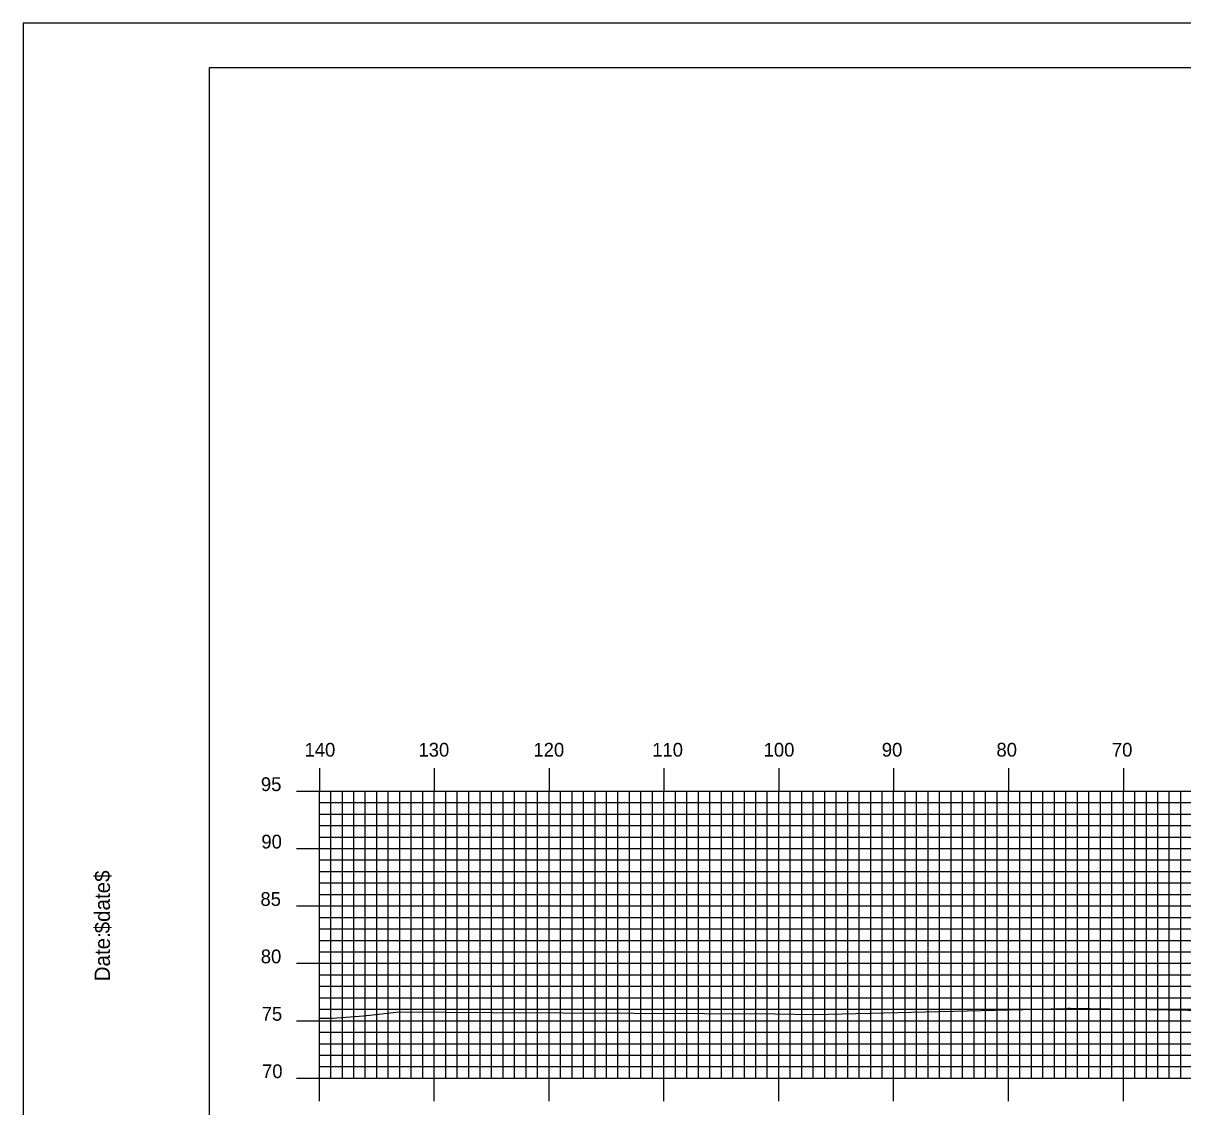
# Model space of a CAD drawing. Extents: x 1776744 to 1777088, y 442591 to 442811.
# Drawn here: x 1776744.5 to 1776845.4, y 442716.2 to 442810.5 of the extents above; entities that cross this region are included whole.
import ezdxf

# ---------------------------------------------------------------- set-up
doc = ezdxf.new("R2010")
doc.units = 0
for name, color, linetype in [('BORDER', 7, 'Continuous'), ('H_V ANNOTATION', 7, 'Continuous'), ('MAJOR', 7, 'Continuous'), ('MINOR', 7, 'Continuous'), ('PLOT BOUNDARY', 7, 'Continuous'), ('S_Roadway_Centerline', 7, 'Continuous')]:
    doc.layers.add(name, color=color, linetype=linetype)

msp = doc.modelspace()

# ---------------------------------------------------------------- linework, layer by layer
at = {"layer": 'BORDER'}
msp.add_lwpolyline([(1776760.65, 442596.67), (1777080.65, 442596.67), (1777080.65, 442806.67), (1776760.65, 442806.67)], close=True, dxfattribs=at)
at = {"layer": 'MAJOR'}
for p, q in [((1776770.25, 442745.67), (1776770.25, 442743.67)), ((1776780.25, 442745.67), (1776780.25, 442743.67)), ((1776790.25, 442745.67), (1776790.25, 442743.67)), ((1776800.25, 442745.67), (1776800.25, 442743.67)), ((1776810.25, 442745.67), (1776810.25, 442743.67)), ((1776820.25, 442745.67), (1776820.25, 442743.67)), ((1776830.25, 442745.67), (1776830.25, 442743.67)), ((1776840.25, 442745.67), (1776840.25, 442743.67)), ((1776768.25, 442743.67), (1776770.25, 442743.67)), ((1776770.25, 442743.67), (1777050.25, 442743.67)), ((1776770.25, 442718.67), (1776770.25, 442743.67)), ((1776770.25, 442718.67), (1776770.25, 442743.67)), ((1776770.25, 442743.67), (1777050.25, 442743.67)), ((1776780.25, 442718.67), (1776780.25, 442743.67)), ((1776790.25, 442718.67), (1776790.25, 442743.67)), ((1776800.25, 442718.67), (1776800.25, 442743.67)), ((1776810.25, 442718.67), (1776810.25, 442743.67)), ((1776820.25, 442718.67), (1776820.25, 442743.67)), ((1776830.25, 442718.67), (1776830.25, 442743.67)), ((1776840.25, 442718.67), (1776840.25, 442743.67)), ((1776768.25, 442738.67), (1776770.25, 442738.67)), ((1776770.25, 442738.67), (1777050.25, 442738.67)), ((1776768.25, 442733.67), (1776770.25, 442733.67)), ((1776770.25, 442733.67), (1777050.25, 442733.67)), ((1776768.25, 442728.67), (1776770.25, 442728.67)), ((1776770.25, 442728.67), (1777050.25, 442728.67)), ((1776768.25, 442723.67), (1776770.25, 442723.67)), ((1776770.25, 442723.67), (1777050.25, 442723.67)), ((1776768.25, 442718.67), (1776770.25, 442718.67)), ((1776770.25, 442718.67), (1777050.25, 442718.67)), ((1776770.25, 442718.67), (1777050.25, 442718.67)), ((1776770.25, 442716.66), (1776770.25, 442718.67)), ((1776780.25, 442716.66), (1776780.25, 442718.67)), ((1776790.25, 442716.66), (1776790.25, 442718.67)), ((1776800.25, 442716.66), (1776800.25, 442718.67)), ((1776810.25, 442716.66), (1776810.25, 442718.67)), ((1776820.25, 442716.66), (1776820.25, 442718.67)), ((1776830.25, 442716.66), (1776830.25, 442718.67)), ((1776840.25, 442716.66), (1776840.25, 442718.67))]:
    msp.add_line(p, q, dxfattribs=at)
at = {"layer": 'MINOR'}
for p, q in [((1776771.25, 442718.67), (1776771.25, 442743.67)), ((1776772.25, 442718.67), (1776772.25, 442743.67)), ((1776773.25, 442718.67), (1776773.25, 442743.67)), ((1776774.25, 442718.67), (1776774.25, 442743.67)), ((1776775.25, 442718.67), (1776775.25, 442743.67)), ((1776776.25, 442718.67), (1776776.25, 442743.67)), ((1776777.25, 442718.67), (1776777.25, 442743.67)), ((1776778.25, 442718.67), (1776778.25, 442743.67)), ((1776779.25, 442718.67), (1776779.25, 442743.67)), ((1776781.25, 442718.67), (1776781.25, 442743.67)), ((1776782.25, 442718.67), (1776782.25, 442743.67)), ((1776783.25, 442718.67), (1776783.25, 442743.67)), ((1776784.25, 442718.67), (1776784.25, 442743.67)), ((1776785.25, 442718.67), (1776785.25, 442743.67)), ((1776786.25, 442718.67), (1776786.25, 442743.67)), ((1776787.25, 442718.67), (1776787.25, 442743.67)), ((1776788.25, 442718.67), (1776788.25, 442743.67)), ((1776789.25, 442718.67), (1776789.25, 442743.67)), ((1776791.25, 442718.67), (1776791.25, 442743.67)), ((1776792.25, 442718.67), (1776792.25, 442743.67)), ((1776793.25, 442718.67), (1776793.25, 442743.67)), ((1776794.25, 442718.67), (1776794.25, 442743.67)), ((1776795.25, 442718.67), (1776795.25, 442743.67)), ((1776796.25, 442718.67), (1776796.25, 442743.67)), ((1776797.25, 442718.67), (1776797.25, 442743.67)), ((1776798.25, 442718.67), (1776798.25, 442743.67)), ((1776799.25, 442718.67), (1776799.25, 442743.67)), ((1776801.25, 442718.67), (1776801.25, 442743.67)), ((1776802.25, 442718.67), (1776802.25, 442743.67)), ((1776803.25, 442718.67), (1776803.25, 442743.67)), ((1776804.25, 442718.67), (1776804.25, 442743.67)), ((1776805.25, 442718.67), (1776805.25, 442743.67)), ((1776806.25, 442718.67), (1776806.25, 442743.67)), ((1776807.25, 442718.67), (1776807.25, 442743.67)), ((1776808.25, 442718.67), (1776808.25, 442743.67)), ((1776809.25, 442718.67), (1776809.25, 442743.67)), ((1776811.25, 442718.67), (1776811.25, 442743.67)), ((1776812.25, 442718.67), (1776812.25, 442743.67)), ((1776813.25, 442718.67), (1776813.25, 442743.67)), ((1776814.25, 442718.67), (1776814.25, 442743.67)), ((1776815.25, 442718.67), (1776815.25, 442743.67)), ((1776816.25, 442718.67), (1776816.25, 442743.67)), ((1776817.25, 442718.67), (1776817.25, 442743.67)), ((1776818.25, 442718.67), (1776818.25, 442743.67)), ((1776819.25, 442718.67), (1776819.25, 442743.67)), ((1776821.25, 442718.67), (1776821.25, 442743.67)), ((1776822.25, 442718.67), (1776822.25, 442743.67)), ((1776823.25, 442718.67), (1776823.25, 442743.67)), ((1776824.25, 442718.67), (1776824.25, 442743.67)), ((1776825.25, 442718.67), (1776825.25, 442743.67)), ((1776826.25, 442718.67), (1776826.25, 442743.67)), ((1776827.25, 442718.67), (1776827.25, 442743.67)), ((1776828.25, 442718.67), (1776828.25, 442743.67)), ((1776829.25, 442718.67), (1776829.25, 442743.67)), ((1776831.25, 442718.67), (1776831.25, 442743.67)), ((1776832.25, 442718.67), (1776832.25, 442743.67)), ((1776833.25, 442718.67), (1776833.25, 442743.67)), ((1776834.25, 442718.67), (1776834.25, 442743.67)), ((1776835.25, 442718.67), (1776835.25, 442743.67)), ((1776836.25, 442718.67), (1776836.25, 442743.67)), ((1776837.25, 442718.67), (1776837.25, 442743.67)), ((1776838.25, 442718.67), (1776838.25, 442743.67)), ((1776839.25, 442718.67), (1776839.25, 442743.67)), ((1776841.25, 442718.67), (1776841.25, 442743.67)), ((1776842.25, 442718.67), (1776842.25, 442743.67)), ((1776843.25, 442718.67), (1776843.25, 442743.67)), ((1776844.25, 442718.67), (1776844.25, 442743.67)), ((1776845.25, 442718.67), (1776845.25, 442743.67)), ((1776770.25, 442742.67), (1777050.25, 442742.67)), ((1776770.25, 442742.67), (1776772.25, 442742.67)), ((1776770.25, 442741.67), (1777050.25, 442741.67)), ((1776770.25, 442741.67), (1776772.25, 442741.67)), ((1776770.25, 442740.67), (1777050.25, 442740.67)), ((1776770.25, 442740.67), (1776772.25, 442740.67)), ((1776770.25, 442739.67), (1777050.25, 442739.67)), ((1776770.25, 442739.67), (1776772.25, 442739.67)), ((1776770.25, 442737.67), (1777050.25, 442737.67)), ((1776770.25, 442737.67), (1776772.25, 442737.67)), ((1776770.25, 442736.67), (1777050.25, 442736.67)), ((1776770.25, 442736.67), (1776772.25, 442736.67)), ((1776770.25, 442735.67), (1777050.25, 442735.67)), ((1776770.25, 442735.67), (1776772.25, 442735.67)), ((1776770.25, 442734.67), (1777050.25, 442734.67)), ((1776770.25, 442734.67), (1776772.25, 442734.67)), ((1776770.25, 442732.67), (1777050.25, 442732.67)), ((1776770.25, 442732.67), (1776772.25, 442732.67)), ((1776770.25, 442731.67), (1777050.25, 442731.67)), ((1776770.25, 442731.67), (1776772.25, 442731.67)), ((1776770.25, 442730.67), (1777050.25, 442730.67)), ((1776770.25, 442730.67), (1776772.25, 442730.67)), ((1776770.25, 442729.67), (1777050.25, 442729.67)), ((1776770.25, 442729.67), (1776772.25, 442729.67)), ((1776770.25, 442727.67), (1777050.25, 442727.67)), ((1776770.25, 442727.67), (1776772.25, 442727.67)), ((1776770.25, 442726.67), (1777050.25, 442726.67)), ((1776770.25, 442726.67), (1776772.25, 442726.67)), ((1776770.25, 442725.67), (1777050.25, 442725.67)), ((1776770.25, 442725.67), (1776772.25, 442725.67)), ((1776770.25, 442724.67), (1777050.25, 442724.67)), ((1776770.25, 442724.67), (1776772.25, 442724.67)), ((1776770.25, 442722.67), (1777050.25, 442722.67)), ((1776770.25, 442722.67), (1776772.25, 442722.67)), ((1776770.25, 442721.67), (1777050.25, 442721.67)), ((1776770.25, 442721.67), (1776772.25, 442721.67)), ((1776770.25, 442720.67), (1777050.25, 442720.67)), ((1776770.25, 442720.67), (1776772.25, 442720.67)), ((1776770.25, 442719.67), (1777050.25, 442719.67)), ((1776770.25, 442719.67), (1776772.25, 442719.67))]:
    msp.add_line(p, q, dxfattribs=at)
at = {"layer": 'PLOT BOUNDARY'}
msp.add_lwpolyline([(1776744.46, 442590.55), (1777084.46, 442590.55), (1777084.46, 442810.55), (1776744.46, 442810.55)], close=True, dxfattribs=at)
at = {"layer": 'S_Roadway_Centerline'}
msp.add_lwpolyline([(1776770.25, 442723.88), (1776771.39, 442723.88), (1776774.1, 442724.09), (1776777.21, 442724.44), (1776785.31, 442724.38), (1776809.94, 442724.27), (1776813.34, 442724.21), (1776835.15, 442724.74), (1776835.43, 442724.75), (1776835.65, 442724.75), (1776849.27, 442724.52)], dxfattribs=at)

# ---------------------------------------------------------------- texts
at = {"layer": 'BORDER'}
for s, p in [('$date$', (1776752.02, 442731.28)), ('Date:', (1776752.02, 442727.1))]:
    msp.add_text(s, height=1.339, rotation=90, dxfattribs=at).set_placement(p)
at = {"layer": 'H_V ANNOTATION'}
for s, p in [('140', (1776768.96, 442746.67)), ('130', (1776778.88, 442746.67)), ('120', (1776788.89, 442746.67)), ('110', (1776799.23, 442746.67)), ('100', (1776808.93, 442746.67)), ('90', (1776819.22, 442746.67)), ('80', (1776829.2, 442746.67)), ('70', (1776839.25, 442746.67)), ('95', (1776765.16, 442743.67)), ('90', (1776765.2, 442738.67)), ('85', (1776765.12, 442733.67)), ('80', (1776765.15, 442728.67)), ('75', (1776765.23, 442723.67)), ('70', (1776765.26, 442718.67))]:
    msp.add_text(s, height=1.2, dxfattribs=at).set_placement(p)
at = {"layer": 'MAJOR'}
msp.add_text('-', height=0.012, dxfattribs=at).set_placement((1776770.24, 442718.67))

doc.saveas('drawing.dxf')
